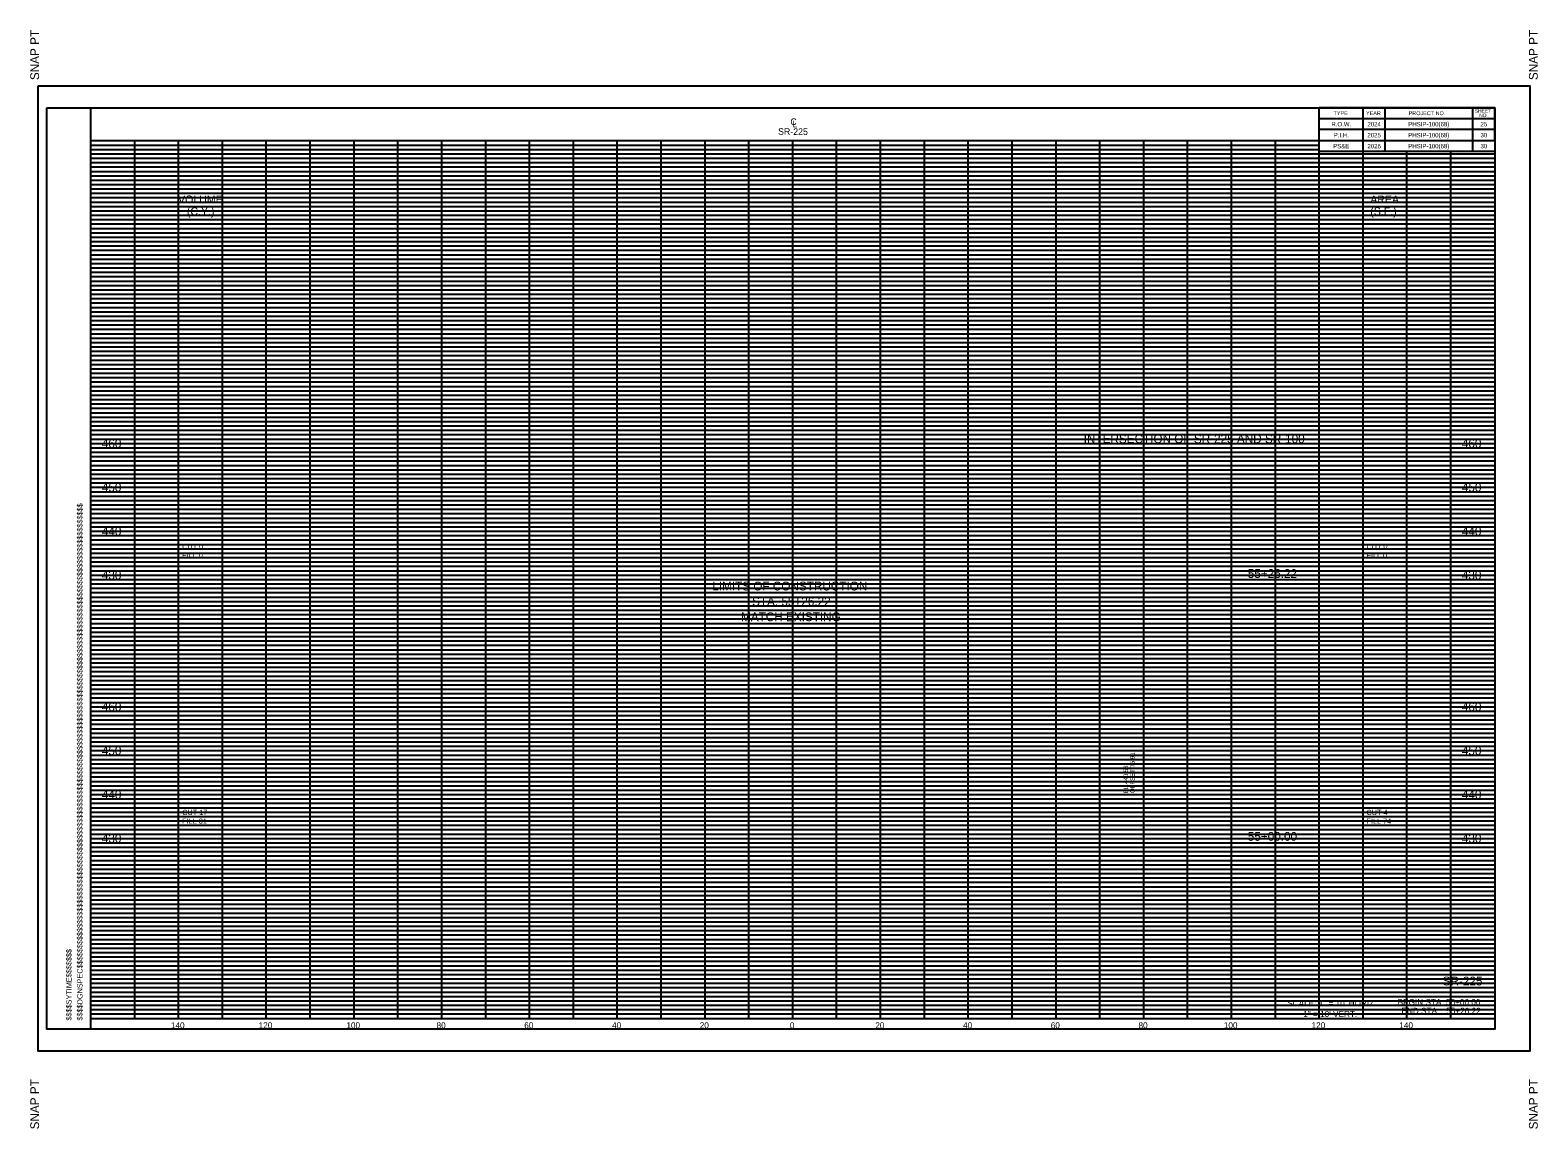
# Model space of a CAD drawing. Extents: x 967 to 1339, y 975 to 1507.
# Drawn here: x 986.2 to 1329.8, y 1256.3 to 1506.6 of the extents above; entities that cross this region are included whole.
import ezdxf

# ---------------------------------------------------------------- set-up
doc = ezdxf.new("R2010")
doc.units = 0
for name, color, linetype in [('Default', 7, 'Continuous'), ('DESIGN - DRAINAGE - Special Ditch Width Text', 7, 'Continuous'), ('DESIGN - SCRATCH - User 1', 7, 'Continuous'), ('DESIGN - SHEET - Corner Text', 7, 'Continuous'), ('DESIGN - SHEET - Light Grid', 7, 'Continuous'), ('DESIGN - SHEET - Linework', 7, 'Continuous'), ('DESIGN - SHEET - Plot Shape', 7, 'Continuous'), ('DESIGN - TYPICAL - Slope Tie Text', 7, 'Continuous'), ('DESIGN - TYPICAL - Text', 7, 'Continuous')]:
    doc.layers.add(name, color=color, linetype=linetype)

msp = doc.modelspace()

# ---------------------------------------------------------------- linework, layer by layer
at = {"layer": 'DESIGN - SCRATCH - User 1'}
for p, q in [((1285, 1485.2), (1285, 1485.2)), ((1292.5, 1485.2), (1292.5, 1485.2)), ((1305, 1485.2), (1305, 1485.2)), ((1317.5, 1485.2), (1317.5, 1485.2)), ((1285, 1482.7), (1285, 1482.7)), ((1292.5, 1482.7), (1292.5, 1482.7)), ((1305, 1482.7), (1305, 1482.7)), ((1317.5, 1482.7), (1317.5, 1482.7)), ((1000, 1281.45), (1000, 1281.45))]:
    msp.add_line(p, q, dxfattribs=at)
at = {"layer": 'DESIGN - SHEET - Light Grid'}
for p, q in [((1000, 1480.45), (1280, 1480.45)), ((1000, 1479.45), (1280, 1479.45)), ((1000, 1478.45), (1320, 1478.45)), ((1000, 1477.45), (1320, 1477.45)), ((1000, 1476.45), (1320, 1476.45)), ((1000, 1475.45), (1320, 1475.45)), ((1000, 1474.45), (1320, 1474.45)), ((1000, 1473.45), (1320, 1473.45)), ((1000, 1472.45), (1320, 1472.45)), ((1000, 1470.45), (1320, 1470.45)), ((1000, 1469.45), (1320, 1469.45)), ((1000, 1468.45), (1320, 1468.45)), ((1000, 1467.45), (1320, 1467.45)), ((1000, 1466.45), (1320, 1466.45)), ((1000, 1465.45), (1320, 1465.45)), ((1000, 1464.45), (1320, 1464.45)), ((1000, 1463.45), (1320, 1463.45)), ((1000, 1462.45), (1320, 1462.45)), ((1000, 1460.45), (1320, 1460.45)), ((1000, 1459.45), (1320, 1459.45)), ((1000, 1458.45), (1320, 1458.45)), ((1000, 1457.45), (1320, 1457.45)), ((1000, 1456.45), (1320, 1456.45)), ((1000, 1455.45), (1320, 1455.45)), ((1000, 1454.45), (1320, 1454.45)), ((1000, 1453.45), (1320, 1453.45)), ((1000, 1452.45), (1320, 1452.45)), ((1000, 1450.45), (1320, 1450.45)), ((1000, 1449.45), (1320, 1449.45)), ((1000, 1448.45), (1320, 1448.45)), ((1000, 1447.45), (1320, 1447.45)), ((1000, 1446.45), (1320, 1446.45)), ((1000, 1445.45), (1320, 1445.45)), ((1000, 1444.45), (1320, 1444.45)), ((1000, 1443.45), (1320, 1443.45)), ((1000, 1442.45), (1320, 1442.45)), ((1000, 1440.45), (1320, 1440.45)), ((1000, 1439.45), (1320, 1439.45)), ((1000, 1438.45), (1320, 1438.45)), ((1000, 1437.45), (1320, 1437.45)), ((1000, 1436.45), (1320, 1436.45)), ((1000, 1435.45), (1320, 1435.45)), ((1000, 1434.45), (1320, 1434.45)), ((1000, 1433.45), (1320, 1433.45)), ((1000, 1432.45), (1320, 1432.45)), ((1000, 1430.45), (1320, 1430.45)), ((1000, 1429.45), (1320, 1429.45)), ((1000, 1428.45), (1320, 1428.45)), ((1000, 1427.45), (1320, 1427.45)), ((1000, 1426.45), (1320, 1426.45)), ((1000, 1425.45), (1320, 1425.45)), ((1000, 1424.45), (1320, 1424.45)), ((1000, 1423.45), (1320, 1423.45)), ((1000, 1422.45), (1320, 1422.45)), ((1000, 1420.45), (1320, 1420.45)), ((1000, 1419.45), (1320, 1419.45)), ((1000, 1418.45), (1320, 1418.45)), ((1000, 1417.45), (1320, 1417.45)), ((1000, 1416.45), (1320, 1416.45)), ((1000, 1415.45), (1320, 1415.45)), ((1000, 1414.45), (1320, 1414.45)), ((1000, 1413.45), (1320, 1413.45)), ((1000, 1412.45), (1320, 1412.45)), ((1000, 1410.45), (1320, 1410.45)), ((1000, 1409.45), (1320, 1409.45)), ((1000, 1408.45), (1320, 1408.45)), ((1000, 1407.45), (1320, 1407.45)), ((1000, 1406.45), (1320, 1406.45)), ((1000, 1405.45), (1320, 1405.45)), ((1000, 1404.45), (1320, 1404.45)), ((1000, 1403.45), (1320, 1403.45)), ((1000, 1402.45), (1320, 1402.45)), ((1000, 1400.45), (1320, 1400.45)), ((1000, 1399.45), (1320, 1399.45)), ((1000, 1398.45), (1320, 1398.45)), ((1000, 1397.45), (1320, 1397.45)), ((1000, 1396.45), (1320, 1396.45)), ((1000, 1395.45), (1320, 1395.45)), ((1000, 1394.45), (1320, 1394.45)), ((1000, 1393.45), (1320, 1393.45)), ((1000, 1392.45), (1320, 1392.45)), ((1000, 1390.45), (1320, 1390.45)), ((1000, 1389.45), (1320, 1389.45)), ((1000, 1388.45), (1320, 1388.45)), ((1000, 1387.45), (1320, 1387.45)), ((1000, 1386.45), (1320, 1386.45)), ((1000, 1385.45), (1320, 1385.45)), ((1000, 1384.45), (1320, 1384.45)), ((1000, 1383.45), (1320, 1383.45)), ((1000, 1382.45), (1320, 1382.45)), ((1000, 1380.45), (1320, 1380.45)), ((1000, 1379.45), (1320, 1379.45)), ((1000, 1378.45), (1320, 1378.45)), ((1000, 1377.45), (1320, 1377.45)), ((1000, 1376.45), (1320, 1376.45)), ((1000, 1375.45), (1320, 1375.45)), ((1000, 1374.45), (1320, 1374.45)), ((1000, 1373.45), (1320, 1373.45)), ((1000, 1372.45), (1320, 1372.45)), ((1000, 1370.45), (1320, 1370.45)), ((1000, 1369.45), (1320, 1369.45)), ((1000, 1368.45), (1320, 1368.45)), ((1000, 1367.45), (1320, 1367.45)), ((1000, 1366.45), (1320, 1366.45)), ((1000, 1365.45), (1320, 1365.45)), ((1000, 1364.45), (1320, 1364.45)), ((1000, 1363.45), (1320, 1363.45)), ((1000, 1362.45), (1320, 1362.45)), ((1000, 1360.45), (1320, 1360.45)), ((1000, 1359.45), (1320, 1359.45)), ((1000, 1358.45), (1320, 1358.45)), ((1000, 1357.45), (1320, 1357.45)), ((1000, 1356.45), (1320, 1356.45)), ((1000, 1355.45), (1320, 1355.45)), ((1000, 1354.45), (1320, 1354.45)), ((1000, 1353.45), (1320, 1353.45)), ((1000, 1352.45), (1320, 1352.45)), ((1000, 1350.45), (1320, 1350.45)), ((1000, 1349.45), (1320, 1349.45)), ((1000, 1348.45), (1320, 1348.45)), ((1000, 1347.45), (1320, 1347.45)), ((1000, 1346.45), (1320, 1346.45)), ((1000, 1345.45), (1320, 1345.45)), ((1000, 1344.45), (1320, 1344.45)), ((1000, 1343.45), (1320, 1343.45)), ((1000, 1342.45), (1320, 1342.45)), ((1000, 1340.45), (1320, 1340.45)), ((1000, 1339.45), (1320, 1339.45)), ((1000, 1338.45), (1320, 1338.45)), ((1000, 1337.45), (1320, 1337.45)), ((1000, 1336.45), (1320, 1336.45)), ((1000, 1335.45), (1320, 1335.45)), ((1000, 1334.45), (1320, 1334.45)), ((1000, 1333.45), (1320, 1333.45)), ((1000, 1332.45), (1320, 1332.45)), ((1000, 1330.45), (1320, 1330.45)), ((1000, 1329.45), (1320, 1329.45)), ((1000, 1328.45), (1320, 1328.45)), ((1000, 1327.45), (1320, 1327.45)), ((1000, 1326.45), (1320, 1326.45)), ((1000, 1325.45), (1320, 1325.45)), ((1000, 1324.45), (1320, 1324.45)), ((1000, 1323.45), (1320, 1323.45)), ((1000, 1322.45), (1320, 1322.45)), ((1000, 1320.45), (1320, 1320.45)), ((1000, 1319.45), (1320, 1319.45)), ((1000, 1318.45), (1320, 1318.45)), ((1000, 1317.45), (1320, 1317.45)), ((1000, 1316.45), (1320, 1316.45)), ((1000, 1315.45), (1320, 1315.45)), ((1000, 1314.45), (1320, 1314.45)), ((1000, 1313.45), (1320, 1313.45)), ((1000, 1312.45), (1320, 1312.45)), ((1000, 1310.45), (1320, 1310.45)), ((1000, 1309.45), (1320, 1309.45)), ((1000, 1308.45), (1320, 1308.45)), ((1000, 1307.45), (1320, 1307.45)), ((1000, 1306.45), (1320, 1306.45)), ((1000, 1305.45), (1320, 1305.45)), ((1000, 1304.45), (1320, 1304.45)), ((1000, 1303.45), (1320, 1303.45)), ((1000, 1302.45), (1320, 1302.45)), ((1000, 1300.45), (1320, 1300.45)), ((1000, 1299.45), (1320, 1299.45)), ((1000, 1298.45), (1320, 1298.45)), ((1000, 1297.45), (1320, 1297.45)), ((1000, 1296.45), (1320, 1296.45)), ((1000, 1295.45), (1320, 1295.45)), ((1000, 1294.45), (1320, 1294.45)), ((1000, 1293.45), (1320, 1293.45)), ((1000, 1292.45), (1320, 1292.45)), ((1000, 1290.45), (1320, 1290.45)), ((1000, 1289.45), (1320, 1289.45)), ((1000, 1288.45), (1320, 1288.45)), ((1000, 1287.45), (1320, 1287.45)), ((1000, 1286.45), (1320, 1286.45)), ((1000, 1285.45), (1320, 1285.45)), ((1000, 1284.45), (1320, 1284.45)), ((1000, 1283.45), (1320, 1283.45)), ((1000, 1282.45), (1320, 1282.45))]:
    msp.add_line(p, q, dxfattribs=at)
at = {"layer": 'DESIGN - SHEET - Linework'}
for p, q in [((1320, 1488.95), (1280, 1488.95)), ((1280, 1481.45), (1280, 1488.95)), ((1290, 1481.45), (1290, 1488.95)), ((1295, 1478.95), (1295, 1488.95)), ((1315, 1478.95), (1315, 1488.95)), ((1320, 1481.45), (1320, 1488.95)), ((1320, 1486.45), (1280, 1486.45)), ((1000, 1481.45), (1320, 1481.45)), ((1010, 1281.45), (1010, 1481.45)), ((1020, 1281.45), (1020, 1481.45)), ((1030, 1281.45), (1030, 1481.45)), ((1040, 1281.45), (1040, 1481.45)), ((1050, 1281.45), (1050, 1481.45)), ((1060, 1281.45), (1060, 1481.45)), ((1070, 1281.45), (1070, 1481.45)), ((1080, 1281.45), (1080, 1481.45)), ((1090, 1281.45), (1090, 1481.45)), ((1100, 1281.45), (1100, 1481.45)), ((1110, 1281.45), (1110, 1481.45)), ((1120, 1281.45), (1120, 1481.45)), ((1130, 1281.45), (1130, 1481.45)), ((1140, 1281.45), (1140, 1481.45)), ((1150, 1281.45), (1150, 1481.45)), ((1160, 1281.45), (1160, 1481.45)), ((1170, 1281.45), (1170, 1481.45)), ((1180, 1281.45), (1180, 1481.45)), ((1190, 1281.45), (1190, 1481.45)), ((1200, 1281.45), (1200, 1481.45)), ((1210, 1281.45), (1210, 1481.45)), ((1220, 1281.45), (1220, 1481.45)), ((1230, 1281.45), (1230, 1481.45)), ((1240, 1281.45), (1240, 1481.45)), ((1250, 1281.45), (1250, 1481.45)), ((1260, 1281.45), (1260, 1481.45)), ((1270, 1281.45), (1270, 1481.45)), ((1320, 1483.95), (1280, 1483.95)), ((1280, 1281.45), (1280, 1481.45)), ((1290, 1281.45), (1290, 1481.45)), ((1320, 1478.95), (1280, 1478.95)), ((1300, 1281.45), (1300, 1478.95)), ((1310, 1281.45), (1310, 1478.95)), ((1000, 1471.45), (1320, 1471.45)), ((1000, 1461.45), (1320, 1461.45)), ((1000, 1451.45), (1320, 1451.45)), ((1000, 1441.45), (1320, 1441.45)), ((1000, 1431.45), (1320, 1431.45)), ((1000, 1421.45), (1320, 1421.45)), ((1000, 1411.45), (1320, 1411.45)), ((1000, 1401.45), (1320, 1401.45)), ((1000, 1391.45), (1320, 1391.45)), ((1000, 1381.45), (1320, 1381.45)), ((1000, 1371.45), (1320, 1371.45)), ((1000, 1361.45), (1320, 1361.45)), ((1000, 1351.45), (1320, 1351.45)), ((1000, 1341.45), (1320, 1341.45)), ((1000, 1331.45), (1320, 1331.45)), ((1000, 1321.45), (1320, 1321.45)), ((1000, 1311.45), (1320, 1311.45)), ((1000, 1301.45), (1320, 1301.45)), ((1000, 1291.45), (1320, 1291.45)), ((1000, 1281.45), (1320, 1281.45))]:
    msp.add_line(p, q, dxfattribs=at)
for points in [[(988, 1493.95), (1328, 1493.95), (1328, 1273.95), (988, 1273.95)], [(1000, 1488.95), (1320, 1488.95), (1320, 1278.95), (1000, 1278.95)]]:
    msp.add_lwpolyline(points, close=True, dxfattribs=at)
at = {"layer": 'DESIGN - SHEET - Plot Shape'}
msp.add_lwpolyline([(990, 1488.95), (1320, 1488.95), (1320, 1278.95), (990, 1278.95)], close=True, dxfattribs=at)

# ---------------------------------------------------------------- texts
at = {"layer": 'Default'}
for s, height, p in [('     460     ', 2, (998.79, 1411.45)), ('     460     ', 2, (1308.79, 1411.45)), ('     450     ', 2, (998.79, 1401.45)), ('     450     ', 2, (1308.79, 1401.45)), ('     440     ', 2, (998.79, 1391.45)), ('     440     ', 2, (1308.79, 1391.45)), ('     430     ', 2, (998.79, 1381.45)), ('     55+26.22     ', 2, (1260, 1381.8)), ('     430     ', 2, (1308.79, 1381.45)), ('     460     ', 2, (998.79, 1351.45)), ('     460     ', 2, (1308.79, 1351.45)), ('     450     ', 2, (998.79, 1341.45)), ('     450     ', 2, (1308.79, 1341.45)), ('     440     ', 2, (998.79, 1331.45)), ('     440     ', 2, (1308.79, 1331.45)), ('     430     ', 2, (998.79, 1321.45)), ('     55+00.00     ', 2, (1260, 1321.91)), ('     430     ', 2, (1308.79, 1321.45)), ('     140     ', 1.4, (1015.65, 1279.15)), ('     120     ', 1.4, (1035.65, 1279.15)), ('     100     ', 1.4, (1055.65, 1279.15)), ('     80     ', 1.4, (1076.2, 1279.15)), ('     60     ', 1.4, (1096.2, 1279.15)), ('     40     ', 1.4, (1116.2, 1279.15)), ('     20     ', 1.4, (1136.2, 1279.15)), ('     0     ', 1.4, (1156.74, 1279.15)), ('     0     ', 1.4, (1156.74, 1279.15)), ('     20     ', 1.4, (1176.2, 1279.15)), ('     40     ', 1.4, (1196.2, 1279.15)), ('     60     ', 1.4, (1216.2, 1279.15)), ('     80     ', 1.4, (1236.2, 1279.15)), ('     100     ', 1.4, (1255.65, 1279.15)), ('     120     ', 1.4, (1275.65, 1279.15)), ('     140     ', 1.4, (1295.65, 1279.15))]:
    msp.add_text(s, height=height, dxfattribs=at).set_placement(p)
at = {"layer": 'DESIGN - DRAINAGE - Special Ditch Width Text'}
for s, p in [('C', (1159.45, 1485.01)), ('L', (1159.94, 1484.46)), ('SR-225', (1156.64, 1482.78))]:
    msp.add_text(s, height=1.5, rotation=359.6675, dxfattribs=at).set_placement(p)
at = {"layer": 'DESIGN - SHEET - Corner Text'}
for s, height, p in [('  SNAP PT', 2, (988.2, 1493.75)), ('  SNAP PT', 2, (1329.8, 1493.75)), ('$$$$DGNSPEC$$$$$$$$$$$$$$$$$$$$$$$$$$$$$$$$$$$$$$$$$$$$$$$$$$$$$$$$$$$$$$$$$$$$$$$$$$$$$$$$$$$$$$$$$$$$$$$$$$$$$$$$$$$$$$$$$$$', 1.2, (998.1, 1280.95)), ('$$$$SYTIME$$$$$$$', 1.2, (995.6, 1280.95)), ('SNAP PT  ', 2, (988.2, 1256.15)), ('SNAP PT  ', 2, (1329.8, 1256.15))]:
    msp.add_text(s, height=height, rotation=90, dxfattribs=at).set_placement(p)
for s, height, p in [('R.O.W.', 1, (1282.77, 1484.7)), ('2024', 1, (1290.98, 1484.7)), ('PHSIP-100(68)', 1, (1300.29, 1484.7)), ('25', 1, (1316.75, 1484.7)), ('P.I.H.', 1, (1283.31, 1482.2)), ('2025', 1, (1290.97, 1482.2)), ('PHSIP-100(68)', 1, (1300.29, 1482.2)), ('30', 1, (1316.76, 1482.2)), ('PS&E', 1, (1283.17, 1479.7)), ('2026', 1, (1290.98, 1479.7)), ('PHSIP-100(68)', 1, (1300.29, 1479.7)), ('30', 1, (1316.76, 1479.7)), ('SR-225', 2, (1308.14, 1288.95)), ('SCALE: 1" = 10\' HORIZ.', 1.4, (1272.71, 1284.19)), ('BEGIN STA. 55+00.00', 1.4, (1297.86, 1284.45)), ('       1" = 10\' VERT.   ', 1.4, (1272.71, 1281.74)), ('END STA.   55+26.22', 1.4, (1298.74, 1282.45))]:
    msp.add_text(s, height=height, dxfattribs=at).set_placement(p)
at = {"layer": 'DESIGN - SHEET - Light Grid'}
for s, height, p in [('TYPE', 0.9, (1283.26, 1487.25)), ('YEAR', 0.9, (1290.66, 1487.25)), ('PROJECT NO.', 0.9, (1300.38, 1487.25)), ('SHEET', 0.8, (1315.47, 1487.8)), ('NO.', 0.8, (1316.47, 1486.8))]:
    msp.add_text(s, height=height, dxfattribs=at).set_placement(p)
at = {"layer": 'DESIGN - TYPICAL - Slope Tie Text'}
for s, p in [('OFFSET 75.91', (1237.91, 1332.78)), ('EL.440.58', (1236.41, 1332.78))]:
    msp.add_text(s, height=1, rotation=90, dxfattribs=at).set_placement(p)
at = {"layer": 'DESIGN - TYPICAL - Text'}
for s, height, p in [('VOLUME', 1.8, (1019.89, 1467.14)), ('AREA ', 1.8, (1291.63, 1467.14)), ('   (C.Y.)', 1.8, (1019.89, 1464.44)), ('(S.F.)', 1.8, (1291.63, 1464.44)), ('INTERSECTION OF SR-225 AND SR-100', 2, (1226.31, 1412.52)), ('CUT 0', 1.2, (1020.83, 1388.35)), ('CUT 0', 1.2, (1290.77, 1388.35)), ('FILL 0', 1.2, (1020.83, 1386.35)), ('FILL 0', 1.2, (1290.77, 1386.35)), ('LIMITS OF CONSTRUCTION', 2, (1141.64, 1378.95)), ('STA. 55+26.22', 2, (1150.72, 1375.45)), ('MATCH EXISTING', 2, (1148.21, 1371.95)), ('CUT 17', 1.2, (1020.83, 1327.77)), ('FILL 81', 1.2, (1020.83, 1325.77)), ('CUT 4', 1.2, (1290.77, 1327.77)), ('FILL 74', 1.2, (1290.77, 1325.77))]:
    msp.add_text(s, height=height, dxfattribs=at).set_placement(p)

doc.saveas('drawing.dxf')
